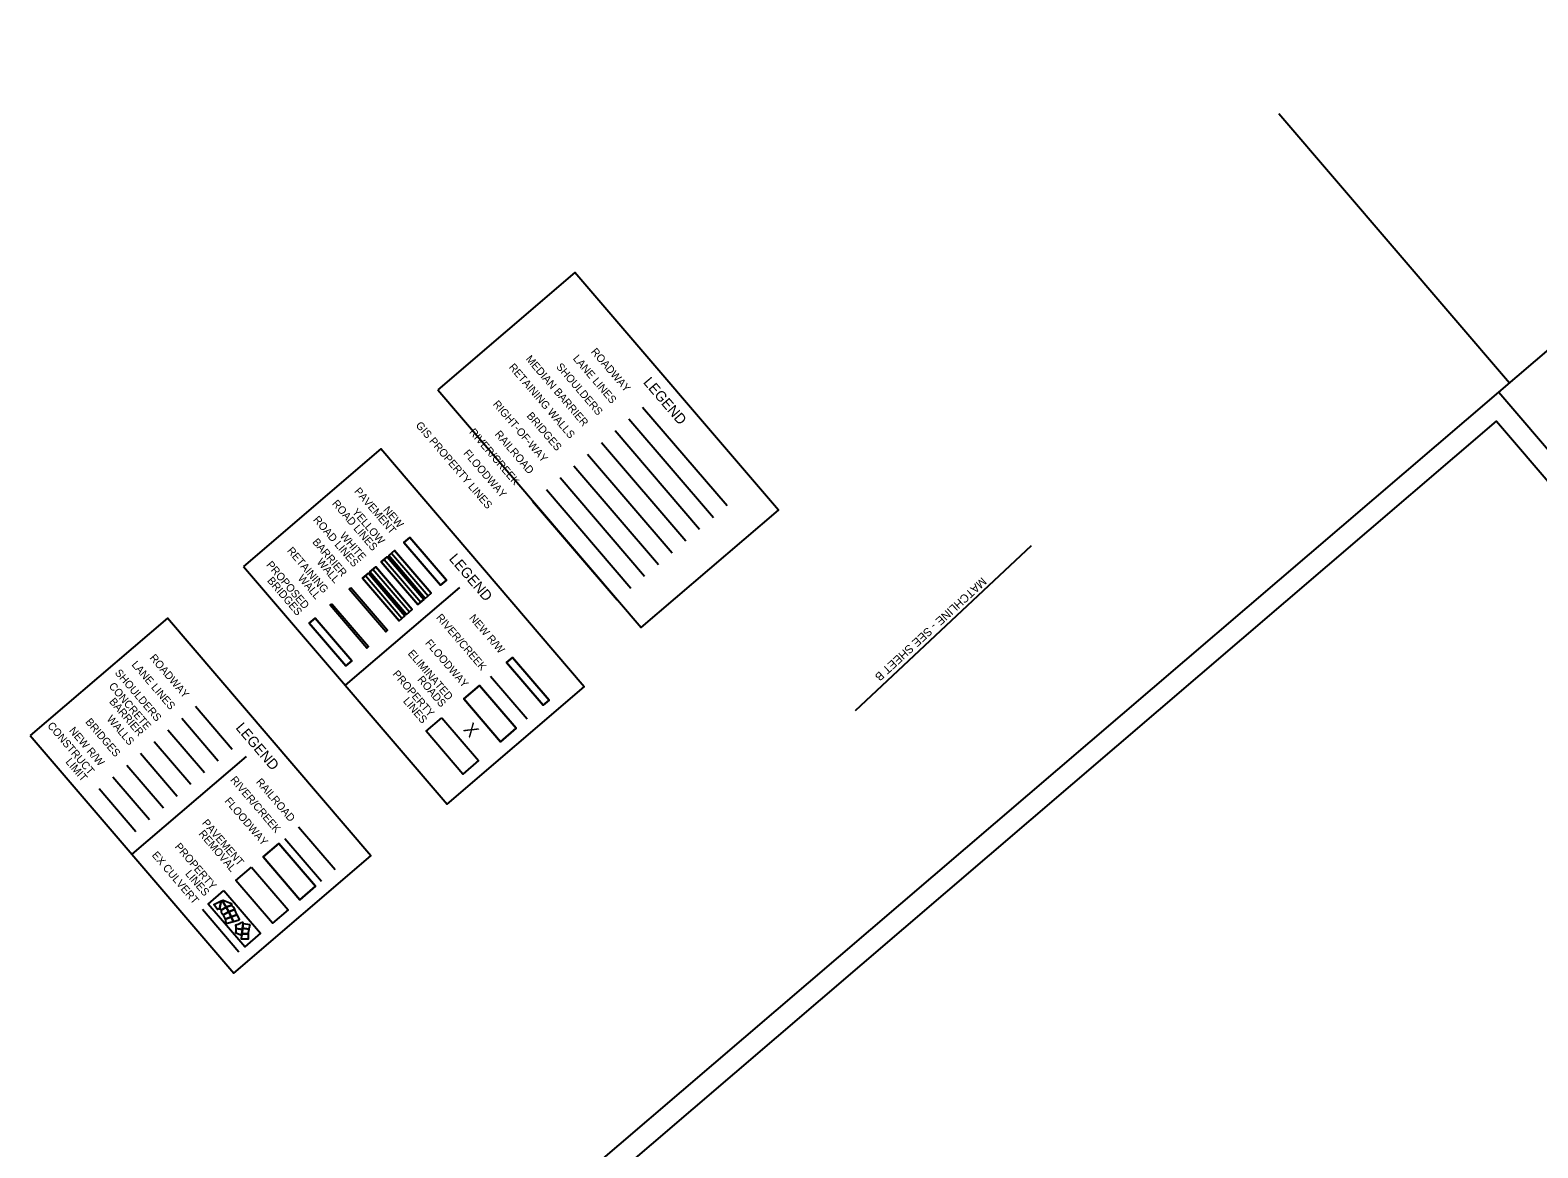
# Model space of a CAD drawing. Extents: x 1941897 to 1978064, y 805467 to 836604.
# Drawn here: x 1941897 to 1949186, y 829350 to 834756 of the extents above; entities that cross this region are included whole.
import ezdxf

# ---------------------------------------------------------------- set-up
doc = ezdxf.new("R2010")
doc.units = 0
for name, color, linetype in [('Default', 7, 'Continuous'), ('RD_EX_DV_Prop', 7, 'Continuous'), ('RD_PD_ALT1_CL', 7, 'Continuous'), ('RD_PD_Bridge', 7, 'Continuous'), ('RD_PD_Final_LnLine', 7, 'Continuous'), ('RD_PD_Final_TrvlWay', 7, 'Continuous'), ('RD_PD_MedBWall', 7, 'Continuous'), ('RD_PD_RW', 7, 'Continuous'), ('RD_PD_WallFill', 7, 'Continuous'), ('RD_QTY_Bridge', 7, 'Continuous'), ('RD_QTY_Surf_Course', 7, 'Continuous'), ('RD_SHT_Bndy', 7, 'Continuous'), ('RD_SHT_IplotShp', 7, 'Continuous'), ('RD_SHT_MatchLine', 7, 'Continuous'), ('RD_SHT_Misc3', 7, 'Continuous'), ('RD_SHT_TX', 7, 'Continuous'), ('RD_Sketch1', 7, 'Continuous')]:
    doc.layers.add(name, color=color, linetype=linetype)

msp = doc.modelspace()

# ---------------------------------------------------------------- linework, layer by layer
at = {"layer": 'Default'}
for points in [[(1942812.7, 830505.4), (1942811.5, 830505.6), (1942809.9, 830505.7), (1942808.3, 830505.6), (1942806.8, 830505.3), (1942805.3, 830504.8), (1942803.8, 830504.1), (1942802.5, 830503.2), (1942785, 830527), (1942820.5, 830544.4)], [(1942843.7, 830514.4), (1942820.5, 830499.9), (1942819.6, 830501.1), (1942818.5, 830502.3), (1942817.3, 830503.3), (1942816, 830504.2), (1942814.5, 830504.8), (1942812.7, 830505.4), (1942820.5, 830544.4), (1942825, 830546.6)], [(1942870.3, 830532), (1942869.9, 830530.2), (1942869.7, 830528.6), (1942869.8, 830527.1), (1942870, 830525.5), (1942870.5, 830524), (1942843.7, 830514.4), (1942825, 830546.6), (1942829.4, 830548.8)], [(1942877, 830516.9), (1942878.2, 830516.2), (1942879.3, 830515.3), (1942880.3, 830514.3), (1942881.2, 830513.2), (1942882.2, 830511), (1942885.1, 830502.7), (1942856.6, 830492.2), (1942843.7, 830514.4), (1942870.5, 830524), (1942871.3, 830522.2), (1942872.1, 830520.8), (1942873.1, 830519.6), (1942874.3, 830518.6), (1942875.6, 830517.6)], [(1942856.6, 830492.2), (1942830.4, 830476.9), (1942829.7, 830477.9), (1942827.5, 830480.6), (1942825.1, 830483.2), (1942824.7, 830483.7), (1942823.9, 830484.8), (1942823.2, 830486), (1942822.7, 830487.3), (1942822.4, 830488.7), (1942822.2, 830490.1), (1942822.3, 830491.5), (1942822.4, 830492.3), (1942822.4, 830493.9), (1942822.2, 830495.4), (1942821.9, 830497), (1942821.3, 830498.4), (1942820.5, 830499.9), (1942843.7, 830514.4)], [(1942868.5, 830467.4), (1942840.6, 830456), (1942840.2, 830457.8), (1942839.7, 830459.2), (1942838.5, 830462.6), (1942837.1, 830465.8), (1942835.5, 830469), (1942833.8, 830472.1), (1942831.8, 830475), (1942830.4, 830476.9), (1942856.6, 830492.2)], [(1942879.9, 830443.3), (1942849.3, 830436.1), (1942848.7, 830436), (1942847.8, 830436), (1942847, 830436.3), (1942846.2, 830436.7), (1942845.6, 830437.3), (1942845.1, 830438), (1942844.8, 830438.8), (1942840.6, 830456), (1942868.5, 830467.4)], [(1942896, 830477.5), (1942868.5, 830467.4), (1942856.6, 830492.2), (1942885.1, 830502.7), (1942889.2, 830490.4)], [(1942879.9, 830443.3), (1942868.5, 830467.4), (1942896, 830477.5), (1942907.1, 830456.7), (1942907.4, 830455.7), (1942907.5, 830454.8), (1942907.4, 830454), (1942907.1, 830453.2), (1942906.6, 830452.5), (1942906, 830451.9), (1942905.2, 830451.4), (1942901.8, 830450.1), (1942896.5, 830448.1), (1942891.1, 830446.3), (1942885.6, 830444.6)], [(1942923.2, 830407), (1942920.7, 830385.9), (1942920.3, 830377.2), (1942890.5, 830388.8), (1942891.2, 830391.7), (1942892, 830395.9), (1942892.6, 830400.1), (1942892.9, 830404.3), (1942893.1, 830408.5), (1942893.1, 830411.7)], [(1942926.6, 830435.3), (1942924, 830413.2), (1942923.2, 830407), (1942893.1, 830411.7), (1942893.1, 830412.8), (1942892.9, 830417), (1942892.4, 830421.2), (1942891.8, 830425.4), (1942891.1, 830429), (1942896.8, 830430.8), (1942902.5, 830432.7), (1942908.1, 830434.8), (1942913.7, 830437.1), (1942919.1, 830439.6), (1942923.3, 830441.7)], [(1942950.7, 830384.9), (1942950.4, 830380.8), (1942950.3, 830379.5), (1942950.3, 830359.8), (1942919.3, 830359.7), (1942920.3, 830377.2), (1942920.7, 830385.9)], [(1942954.1, 830407.6), (1942953.4, 830404.1), (1942952.3, 830398.3), (1942951.5, 830392.5), (1942950.8, 830386.7), (1942950.7, 830384.9), (1942920.7, 830385.9), (1942923.2, 830407), (1942924, 830413.2)], [(1942960.8, 830430.4), (1942959.5, 830426.7), (1942957.7, 830421.2), (1942956.1, 830415.5), (1942954.6, 830409.8), (1942954.1, 830407.6), (1942924, 830413.2), (1942926.6, 830435.3)]]:
    msp.add_lwpolyline(points, close=True, dxfattribs=at)
at = {"layer": 'RD_EX_DV_Prop'}
msp.add_lwpolyline([(1943886.9, 831429.9), (1944063.9, 831223.2), (1943987.9, 831158.1), (1943810.9, 831364.9)], close=True, dxfattribs=at)
at = {"layer": 'RD_PD_ALT1_CL'}
for p, q in [((1943644.5, 832226.9), (1943821.5, 832020.2)), ((1943608.9, 832196.5), (1943785.9, 831989.7))]:
    msp.add_line(p, q, dxfattribs=at)
at = {"layer": 'RD_PD_Bridge'}
msp.add_lwpolyline([(1943274.6, 831912.2), (1943451.6, 831705.4), (1943423.1, 831681), (1943246.1, 831887.8)], close=True, dxfattribs=at)
at = {"layer": 'RD_PD_Final_LnLine'}
for p, q in [((1948997.3, 833005.4), (1951042.2, 834756.1)), ((1949048.5, 833049.3), (1947933.5, 834351.7)), ((1943517.5, 832118.3), (1943694.5, 831911.5))]:
    msp.add_line(p, q, dxfattribs=at)
at = {"layer": 'RD_PD_Final_TrvlWay'}
msp.add_line((1943553.1, 832148.7), (1943730.1, 831942), dxfattribs=at)
at = {"layer": 'RD_PD_MedBWall'}
msp.add_lwpolyline([(1943447.3, 832060), (1943624.3, 831853.3), (1943615.8, 831846), (1943438.8, 832052.7)], close=True, dxfattribs=at)
at = {"layer": 'RD_PD_RW'}
msp.add_lwpolyline([(1944228.6, 831722.4), (1944405.6, 831515.6), (1944377.1, 831491.3), (1944200.1, 831698)], close=True, dxfattribs=at)
msp.add_lwpolyline([(1944200.1, 831698), (1944377.1, 831491.3), (1944405.6, 831515.6), (1944228.6, 831722.4), (1944200.1, 831698)], dxfattribs=at)
at = {"layer": 'RD_PD_WallFill'}
msp.add_lwpolyline([(1943356, 831981.8), (1943533, 831775.1), (1943524.5, 831767.7), (1943347.4, 831974.5)], close=True, dxfattribs=at)
at = {"layer": 'RD_QTY_Bridge'}
msp.add_lwpolyline([(1943246.1, 831887.8), (1943423.1, 831681), (1943451.6, 831705.4), (1943274.6, 831912.2), (1943246.1, 831887.8)], dxfattribs=at)
at = {"layer": 'RD_QTY_Surf_Course'}
for points in [[(1943732.3, 832302.1), (1943909.3, 832095.3), (1943880.8, 832071), (1943703.8, 832277.7)], [(1943623.1, 832208.7), (1943800.1, 832001.9), (1943771.6, 831977.5), (1943594.6, 832184.3)], [(1943658.7, 832239.1), (1943835.7, 832032.4), (1943807.2, 832008), (1943630.2, 832214.7)], [(1943531.8, 832130.4), (1943708.8, 831923.7), (1943680.3, 831899.3), (1943503.3, 832106.1)], [(1943567.4, 832160.9), (1943744.4, 831954.2), (1943715.9, 831929.8), (1943538.9, 832136.5)]]:
    msp.add_lwpolyline(points, close=True, dxfattribs=at)
for points in [[(1943703.8, 832277.7), (1943880.8, 832071), (1943909.3, 832095.3), (1943732.3, 832302.1), (1943703.8, 832277.7)], [(1943594.6, 832184.3), (1943771.6, 831977.5), (1943800.1, 832001.9), (1943623.1, 832208.7), (1943594.6, 832184.3)], [(1943630.2, 832214.7), (1943807.2, 832008), (1943835.7, 832032.4), (1943658.7, 832239.1), (1943630.2, 832214.7)], [(1943503.3, 832106.1), (1943680.3, 831899.3), (1943708.8, 831923.7), (1943531.8, 832130.4), (1943503.3, 832106.1)], [(1943538.9, 832136.5), (1943715.9, 831929.8), (1943744.4, 831954.2), (1943567.4, 832160.9), (1943538.9, 832136.5)]]:
    msp.add_lwpolyline(points, dxfattribs=at)
at = {"layer": 'RD_SHT_Bndy'}
for p, q in [((1943971.9, 832059.9), (1943420.2, 831587.6)), ((1942940.6, 831242.4), (1942388.9, 830770.2))]:
    msp.add_line(p, q, dxfattribs=at)
for points in [[(1943867.1, 833016), (1944851.4, 831866.3), (1945514.7, 832434.2), (1944530.4, 833583.9)], [(1960707.9, 808409.5), (1943668.8, 828312), (1948986.3, 832864.4), (1966025.3, 812961.9)], [(1942928.1, 832162.4), (1943912.4, 831012.7), (1944575.7, 831580.6), (1943591.4, 832730.3)], [(1941896.8, 831345), (1942881.1, 830195.3), (1943544.4, 830763.2), (1942560.1, 831912.9)]]:
    msp.add_lwpolyline(points, close=True, dxfattribs=at)
at = {"layer": 'RD_SHT_IplotShp'}
msp.add_lwpolyline([(1960696.9, 808268.5), (1943527.9, 828323), (1948997.3, 833005.4), (1966166.3, 812950.9)], close=True, dxfattribs=at)
at = {"layer": 'RD_SHT_MatchLine'}
msp.add_line((1946737.1, 832262.3), (1945885.4, 831464), dxfattribs=at)
at = {"layer": 'RD_Sketch1'}
for p, q in [((1944857.9, 832933.2), (1945266.2, 832456.3)), ((1944791.5, 832876.3), (1945199.8, 832399.4)), ((1944725, 832819.4), (1945133.3, 832342.5)), ((1944658.5, 832762.5), (1945066.8, 832285.6)), ((1944525.6, 832648.7), (1944933.9, 832171.8)), ((1944592.1, 832705.6), (1945000.4, 832228.7)), ((1944459.1, 832591.8), (1944867.4, 832114.8)), ((1944392.7, 832534.9), (1944801, 832057.9)), ((1944326.2, 832478), (1944734.5, 832001)), ((1944123, 831632), (1944300, 831425.3)), ((1942696, 831486), (1942873, 831279.3)), ((1942629.5, 831429.1), (1942806.5, 831222.3)), ((1942563.1, 831372.2), (1942740.1, 831165.4)), ((1942430.1, 831258.4), (1942607.1, 831051.6)), ((1942496.6, 831315.3), (1942673.6, 831108.5)), ((1942363.7, 831201.5), (1942540.7, 830994.7)), ((1942297.2, 831144.6), (1942474.2, 830937.8)), ((1942230.7, 831087.7), (1942407.7, 830880.9)), ((1943194.6, 830903.6), (1943371.7, 830696.8)), ((1943128.2, 830846.6), (1943305.2, 830639.9)), ((1942729.4, 830505.2), (1942906.4, 830298.5))]:
    msp.add_line(p, q, dxfattribs=at)
for points in [[(1944069.6, 831586.3), (1944246.6, 831379.6), (1944170.6, 831314.5), (1943993.6, 831521.3)], [(1943099.7, 830822.3), (1943276.7, 830615.5), (1943200.7, 830550.5), (1943023.7, 830757.2)], [(1942966.8, 830708.4), (1943143.8, 830501.7), (1943067.8, 830436.7), (1942890.8, 830643.4)], [(1942833.8, 830594.6), (1943010.8, 830387.9), (1942934.9, 830322.8), (1942757.9, 830529.6)]]:
    msp.add_lwpolyline(points, close=True, dxfattribs=at)
for points in [[(1943993.6, 831521.3), (1944170.6, 831314.5), (1944246.6, 831379.6), (1944069.6, 831586.3), (1943993.6, 831521.3)], [(1943023.7, 830757.2), (1943200.7, 830550.5), (1943276.7, 830615.5), (1943099.7, 830822.3), (1943023.7, 830757.2)]]:
    msp.add_lwpolyline(points, dxfattribs=at)

# ---------------------------------------------------------------- texts
at = {"layer": 'RD_SHT_Misc3'}
msp.add_text('X', height=62.5, rotation=310.56753, dxfattribs=at).set_placement((1943987.4, 831372.5))
at = {"layer": 'RD_SHT_TX'}
for s, height, rotation, p in [('ROADWAY', 37.5, 310.56753, (1944605.7, 833199)), ('RETAINING WALLS', 37.5, 310.56753, (1944208.7, 833124.6)), ('MEDIAN BARRIER', 37.5, 310.56753, (1944290, 833164.2)), ('SHOULDERS', 37.5, 310.56753, (1944437.3, 833126.6)), ('LANE LINES', 37.5, 310.56753, (1944518.5, 833166.3)), ('LEGEND', 50, 310.56753, (1944858, 833051.3)), ('RIGHT-OF-WAY', 37.5, 310.56753, (1944131.5, 832945.6)), ('GIS PROPERTY LINES', 37.5, 310.56753, (1943758.3, 832843.4)), ('BRIDGES', 37.5, 310.56753, (1944295, 832889.2)), ('RIVER/CREEK', 37.5, 310.56753, (1944016.9, 832810.4)), ('RAILROAD', 37.5, 310.56753, (1944140.8, 832800.2)), ('FLOODWAY', 37.5, 310.56753, (1943989.1, 832708.3)), ('PAVEMENT', 37.5, 310.56753, (1943461.6, 832524.5)), ('ROAD LINES', 37.5, 310.56753, (1943354.2, 832465.1)), ('YELLOW', 37.5, 310.56753, (1943450.9, 832424.2)), ('NEW', 37.5, 310.56753, (1943601.2, 832433.5)), ('ROAD LINES', 37.5, 310.56753, (1943262.8, 832386.9)), ('BARRIER', 37.5, 310.56753, (1943258.7, 832278.9)), ('WHITE', 37.5, 310.56753, (1943391.4, 832308.8)), ('RETAINING', 37.5, 310.56753, (1943136.5, 832236.8)), ('WALL', 37.5, 310.56753, (1943280.1, 832181.9)), ('LEGEND', 50, 310.56753, (1943919, 832197.8)), ('PROPOSED', 37.5, 310.56753, (1943036.3, 832168.8)), ('WALL', 37.5, 310.56753, (1943188.7, 832103.7)), ('BRIDGES', 37.5, 310.56753, (1943040.3, 832092.1)), ('MATCHLINE - SEE SHEET B', 40, 222.56753, (1946498.1, 832112.4)), ('RIVER/CREEK', 37.5, 310.56753, (1943857, 831913.8)), ('NEW R/W ', 37.5, 310.56753, (1944017.3, 831911.5)), ('ELIMINATED', 37.5, 310.56753, (1943720.2, 831739.8)), ('FLOODWAY', 37.5, 310.56753, (1943804.4, 831790.4)), ('LANE LINES', 37.5, 310.56753, (1942384.9, 831686)), ('ROADWAY', 37.5, 310.56753, (1942472.2, 831718.6)), ('SHOULDERS', 37.5, 310.56753, (1942303.8, 831646.3)), ('PROPERTY ', 37.5, 310.56753, (1943646.8, 831640.7)), ('ROADS', 37.5, 310.56753, (1943766.5, 831613.7)), ('CONCRETE', 37.5, 310.56753, (1942274.5, 831582)), ('BARRIER', 37.5, 310.56753, (1942276.6, 831507.3)), ('LINES', 37.5, 310.56753, (1943697.3, 831509.7)), ('CONSTRUCT', 37.5, 310.56753, (1941977.7, 831390.4)), ('BRIDGES', 37.5, 310.56753, (1942161.4, 831408.9)), ('WALLS', 37.5, 310.56753, (1942264.7, 831422.8)), ('LEGEND', 50, 310.56753, (1942887.7, 831380.3)), ('NEW R/W ', 37.5, 310.56753, (1942082.5, 831366.5)), ('LIMIT', 37.5, 310.56753, (1942065.4, 831215.9)), ('RIVER/CREEK', 37.5, 310.56753, (1942862.3, 831128.4)), ('RAILROAD', 37.5, 310.56753, (1942986.2, 831118.2)), ('FLOODWAY', 37.5, 310.56753, (1942834.5, 831026.3)), ('REMOVAL', 37.5, 310.56753, (1942709, 830867.8)), ('PAVEMENT', 37.5, 310.56753, (1942725.7, 830920.3)), ('PROPERTY ', 37.5, 310.56753, (1942593.7, 830805.4)), ('EX CULVERT', 37.5, 310.56753, (1942482.8, 830764.5)), ('LINES', 37.5, 310.56753, (1942644.2, 830674.4))]:
    msp.add_text(s, height=height, rotation=rotation, dxfattribs=at).set_placement(p)

doc.saveas('drawing.dxf')
